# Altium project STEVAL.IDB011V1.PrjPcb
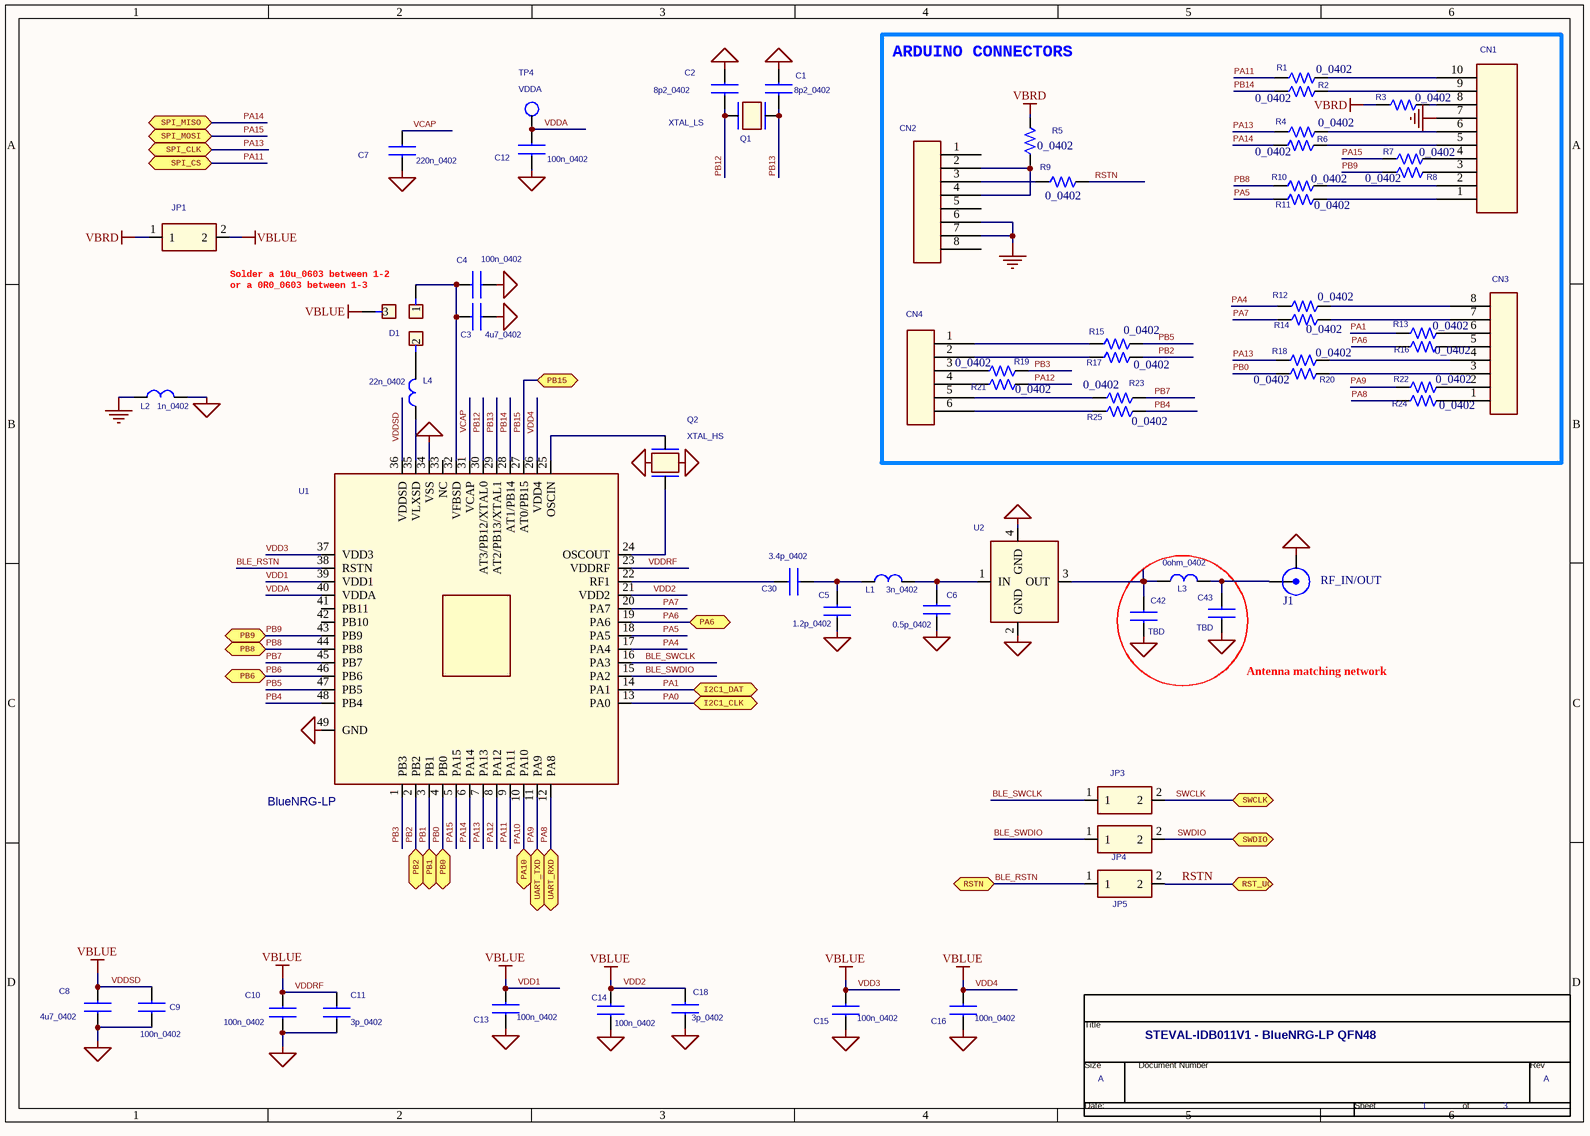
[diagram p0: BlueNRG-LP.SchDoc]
3 sheets, 158 parts. Net scope: flat (ports and power ports of the same name join across sheets).
Board file: STEVAL-IDB011V1.PcbDoc
Sheets:
  BlueNRG-LP.SchDoc
  Supply.SchDoc
  USB_MICRO.SchDoc

## Sheet BlueNRG-LP.SchDoc
size 297 x 209 mm

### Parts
(Parts that share a designator on the sheet are numbered #1, #2 ... from top to bottom, then left to right.)
*#1  Page Count: 3  Page Number: 1  Page Size: A  Title: STEVAL-IDB011V1 - BlueNRG-LP QFN48  (hidden comment: TitleBlock0)  (graphical)
C1  8p2_0402  [0402_CAP_NP]
C2  8p2_0402  [0402_CAP_NP]
C3  4u7_0402  [0402_CAP_NP]
C4  100n_0402  [0402_CAP_NP]
C5  1.2p_0402  [0402_CAP_NP]
C6  0.5p_0402  [0402_CAP_NP]
C7  220n_0402  [0402_CAP_NP]
C8  4u7_0402  [0402_CAP_NP]
C9  100n_0402  [0402_CAP_NP]
C10  100n_0402  [0402_CAP_NP]
C11  3p_0402  [0402_CAP_NP]
C12  100n_0402  [0402_CAP_NP]
C13  100n_0402  [0402_CAP_NP]
C14  100n_0402  [0402_CAP_NP]
C15  100n_0402  [0402_CAP_NP]
C16  100n_0402  [0402_CAP_NP]
C18  3p_0402  [0402_CAP_NP]
C30  3.4p_0402  [0402_CAP_NP]
C42  TBD  [0402_CAP_NP]
C43  TBD  [0402_CAP_NP]
CN1  CON10  [HDR1X10]  (value not drawn)
CN2  CON8  [HDR1X8]  (value not drawn)
CN3  CON8  [HDR1X8]  (value not drawn)
CN4  CON6  [HDR1X6]  (value not drawn)
D1  DEV3L  [DEV3L0603]  (value not drawn)
J1  RF_IN/OUT  [SMA Johonson 142-0701-841]
JP1  JUMPER 2  [HDR 2 X 1 M]  (value not drawn)
JP3  JUMPER 2  [HDR 2 X 1 M]  (value not drawn)
JP4  JUMPER 2  [HDR 2 X 1 M]  (value not drawn)
JP5  JUMPER 2  [HDR 2 X 1 M]  (value not drawn)
L1  3n_0402  [0402-A]
L2  1n_0402  [0402-A]
L3  0ohm_0402  [0402-A]
L4  22n_0402  [0402-A]
Q1  XTAL_LS  [NX2012SA]
Q2  XTAL_HS  [NX2016SA]
R1  0_0402
R2  0_0402
R3  0_0402
R4  0_0402
R5  0_0402
R6  0_0402
R7  0_0402
R8  0_0402
R9  0_0402
R10  0_0402
R11  0_0402
R12  0_0402
R13  0_0402
R14  0_0402
R15  0_0402
R16  0_0402
R17  0_0402
R18  0_0402
R19  0_0402
R20  0_0402
R21  0_0402
R22  0_0402
R23  0_0402
R24  0_0402
R25  0_0402
TP4  VDDA  [FIDUCIAL]
U1  BlueNRG-LP  [QFN48_6X6]
U2  (no value)  [DLF162500LT]

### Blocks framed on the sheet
ARDUINO CONNECTORS: CN1-CN4 R1-R25

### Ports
I2C1_CLK (bidir), I2C1_DAT (bidir), PA6 (bidir), PA10 (bidir), PB0 (bidir), PB1 (bidir), PB2 (bidir), PB6 (bidir), PB8 (bidir), PB9 (bidir), PB15 (bidir), RST_UC (bidir), RSTN (bidir), SPI_CLK (bidir), SPI_CS (bidir), SPI_MISO (bidir), SPI_MOSI (bidir), SWCLK (bidir), SWDIO (bidir), UART_RXD (bidir), UART_TXD (bidir)

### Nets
GND: CN1.7 CN2.6 CN2.7 L2.1
GND_RF: C1.1 C2.1 C3.1 C4.1 C5.1 C6.1 C7.1 C8.1 C9.1 C10.1 C11.1 C12.1 C13.1 C14.1 C15.1 C16.1 C18.1 C42.1 C43.1 J1.2(Y) L2.2 Q2.2 Q2.4(gnd1) U1.34(VSS) U1.49(GND) U2.2(GND) U2.4(GND)
VBRD: JP1.1 R3.1 R5.2  [project net VDD_1]
VDD1: C8.2 C9.2 C10.2 C11.2 C13.2 C14.2 C15.2 C16.2 C18.2 D1.3 JP1.2 U1.21(VDD2) U1.23(VDDRF) U1.26(VDD4) U1.36(VDDSD) U1.37(VDD3) U1.39(VDD1)  [also labelled VBLUE, VDD2, VDD3, VDD4, VDDRF, VDDSD]
BLE_RSTN: JP5.1 U1.38(RSTN) ; port RSTN
BLE_SWCLK: JP3.1 U1.16(PA3)
BLE_SWDIO: JP4.1 U1.15(PA2)
PA0: U1.13(PA0) ; port I2C1_CLK
PA1: R13.1 U1.14(PA1) ; port I2C1_DAT
PA4: R12.1 U1.17(PA4)
PA5: R11.1 U1.18(PA5)
PA6: R16.1 U1.19(PA6) ; port PA6
PA7: R14.1 U1.20(PA7)
PA8: R24.1 U1.12(PA8) ; port UART_RXD
PA9: R22.1 U1.11(PA9) ; port UART_TXD
PA10: U1.10(PA10) ; port PA10
PA11: R1.1 U1.9(PA11) ; port SPI_CS
PA12: R21.2 U1.8(PA12)
PA13: R4.1 R18.1 U1.7(PA13) ; port SPI_CLK
PA14: R6.1 U1.6(PA14) ; port SPI_MISO
PA15: R7.1 U1.5(PA15) ; port SPI_MOSI
PB0: R20.1 U1.4(PB0) ; port PB0
PB1: U1.3(PB1) ; port PB1
PB2: R17.2 U1.2(PB2) ; port PB2
PB3: R19.2 U1.1(PB3)
PB4: R25.2 U1.48(PB4)
PB5: R15.2 U1.47(PB5)
PB6: U1.46(PB6) ; port PB6
PB7: R23.2 U1.45(PB7)
PB8: R10.1 U1.44(PB8) ; port PB8
PB9: R8.1 U1.43(PB9) ; port PB9
PB12: C2.2 Q1.1 U1.30(AT3/PB12/XTAL0)
PB13: C1.2 Q1.2 U1.29(AT2/PB13/XTAL1)
PB14: R2.1 U1.28(AT1/PB14)
PB15: U1.27(AT0/PB15) ; port PB15
RSTN: JP5.2 R9.2 ; port RST_UC
SWCLK: JP3.2 ; port SWCLK
SWDIO: JP4.2 ; port SWDIO
VCAP: C7.2 U1.31(VCAP)
VDDA: C12.2 TP4.1(TP) U1.40(VDDA)
NetC3_2: C3.2 C4.2 D1.1 U1.32(VFBSD)
NetC5_2: C5.2 C30.1 L1.1
NetC6_2: C6.2 L1.2 U2.1(IN)
NetC30_2: C30.2 U1.22(RF1)
NetC42_2: C42.2 L3.1 U2.3(OUT)
NetC43_2: C43.2 J1.1(X) L3.2
NetCN1_1: CN1.1 R11.2
NetCN1_2: CN1.2 R10.2
NetCN1_3: CN1.3 R8.2
NetCN1_4: CN1.4 R7.2
NetCN1_5: CN1.5 R6.2
NetCN1_6: CN1.6 R4.2
NetCN1_8: CN1.8 R3.2
NetCN1_9: CN1.9 R2.2
NetCN1_10: CN1.10 R1.2
NetCN2_2: CN2.2 CN2.4 R5.1
NetCN2_3: CN2.3 R9.1
NetCN3_1: CN3.1 R24.2
NetCN3_2: CN3.2 R22.2
NetCN3_3: CN3.3 R20.2
NetCN3_4: CN3.4 R18.2
NetCN3_5: CN3.5 R16.2
NetCN3_6: CN3.6 R13.2
NetCN3_7: CN3.7 R14.2
NetCN3_8: CN3.8 R12.2
NetCN4_1: CN4.1 R15.1
NetCN4_2: CN4.2 R17.1
NetCN4_3: CN4.3 R19.1
NetCN4_4: CN4.4 R21.1
NetCN4_5: CN4.5 R23.1
NetCN4_6: CN4.6 R25.1
NetD1_2: D1.2 L4.2
NetL4_1: L4.1 U1.35(VLXSD)
NetQ2_1: Q2.1 U1.25(OSCIN)
NetQ2_3: Q2.3 U1.24(OSCOUT)

Not connected (* = marked no-connect by the designer): CN2 1 5 8; U1 33(NC) 41(PB11) 42(PB10)

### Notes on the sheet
- (near D1) Solder a 10u_0603 between 1-2
  or a 0R0_0603 between 1-3
- (near C43) Antenna matching network

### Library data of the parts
*#1 = TitleBlock0: Doc: BLUENRG-248 APPLICATION BOARD
C1 C6 C10 C12 C13 = MURATA GRM36: COMPSIDE: TOP; COMPLOC: [-1955.000,605.000]; COMPROT: 180; COMPGROUP: 0; COMPFIXED: NO; COMPHEIGHT: 0.000
C2-C5 C7-C9 C11 C14-C16 C18 C30 C42 C43 = MURATA GRM36: COMPHEIGHT: 0.000; MEMORY: NO; COMPGROUP: 0; COMPROT: 180; COMPLOC: [-1955.000,605.000]; COMPSIDE: TOP
D1 = DEV3L_0
J1 = SMA_Molex: 50 Ohms, SMA Jack Receptacle, Edge Mount, .25µm Gold (Au) Plating; Manufacturer: Molex; Manufacturer’s ordering code / Orderable Part Number: 73251-1150; STEVAL: FKIxxx; Value: SMA_RF
JP1 JP3-JP5 = Buzzer
L1-L4 = IND_short
Q1 = QUARZO
Q2 = NX3225SA: COMPSIDE: TOP; COMPLOC: [-2158.000,974.000]; COMPROT: 180; COMPGROUP: 0; COMPFIXED: NO; COMPHEIGHT: 0.000
R1-R25 = R_Dup1: PSpiceTemplate: R^@REFDES %1 %2 ?TOLERANCE¦R^@REFDES¦ @VALUE  ?TOLERANCE¦\n.model R^@REFDES RES R=1 DEV=@TOLERANCE%¦
TP4 = T POINT R: COMPHEIGHT: 10.000; MEMORY: NO; COMPGROUP: 0; COMPROT: 270; COMPLOC: [734.867,493.467]; COMPSIDE: TOP
U1 = BlueNRG-LP_QFN48_0
U2 = DLF162500LT

## Sheet Supply.SchDoc
size 297 x 209 mm
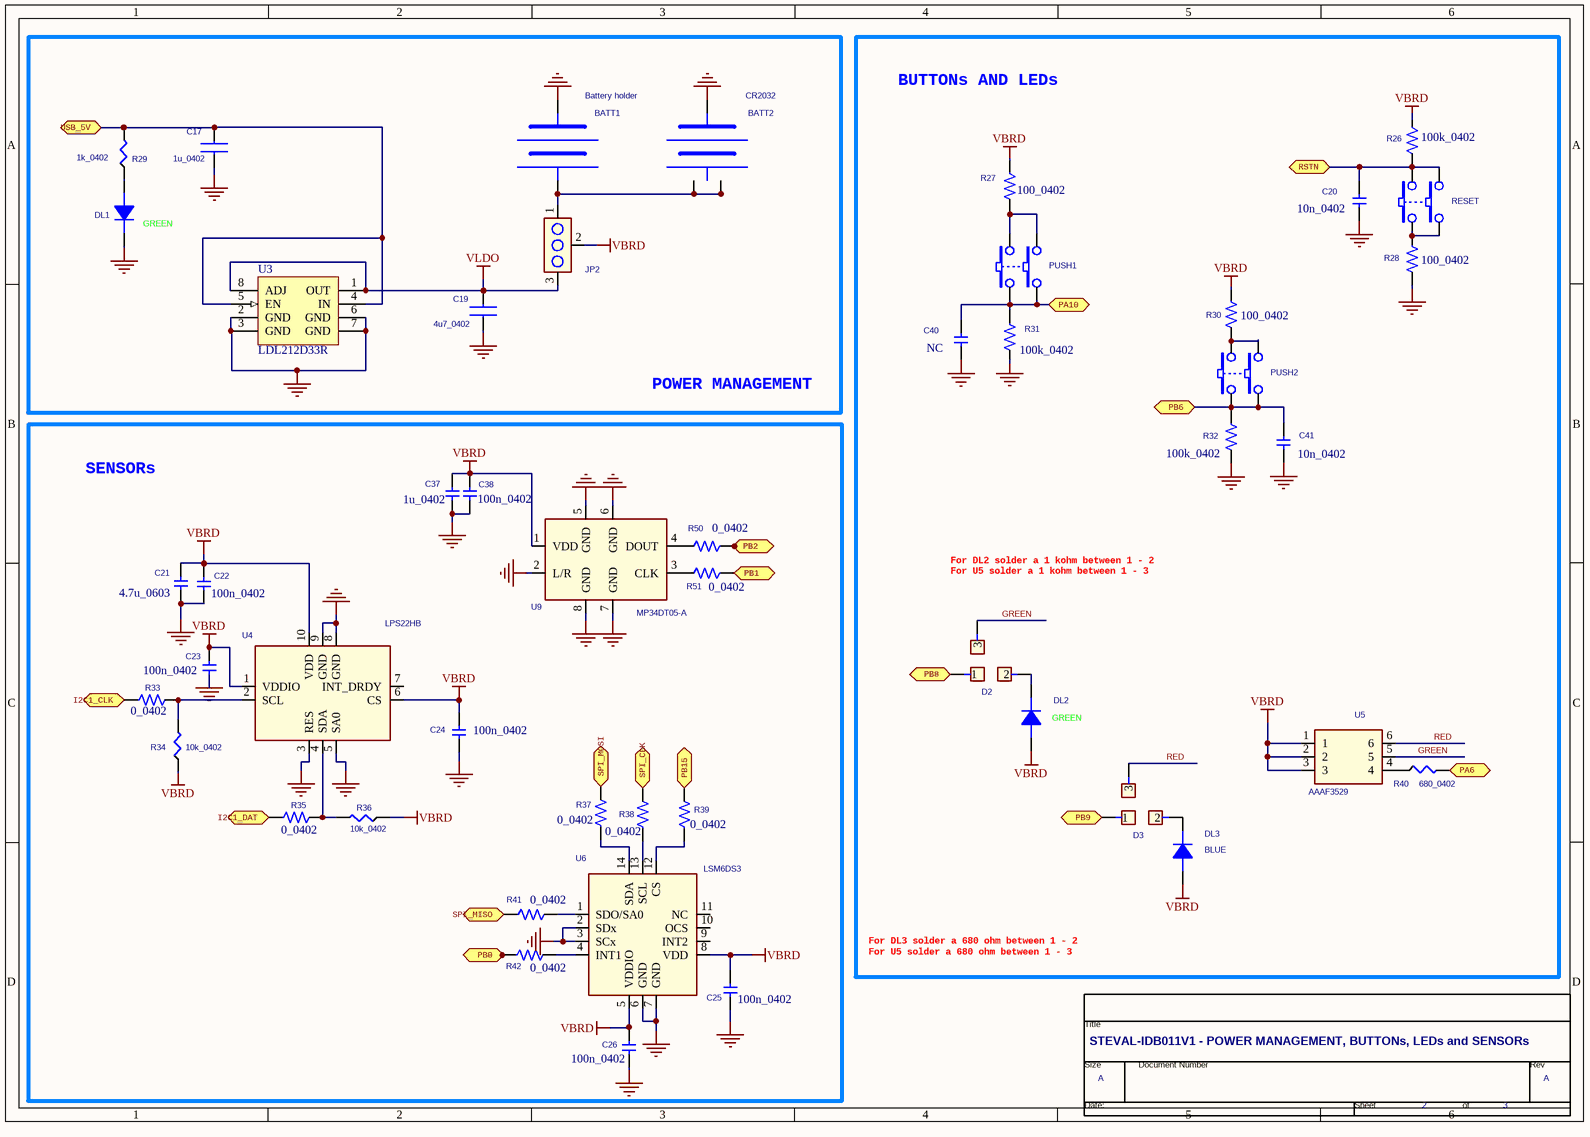
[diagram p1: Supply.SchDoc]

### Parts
(Parts that share a designator on the sheet are numbered #1, #2 ... from top to bottom, then left to right.)
*#2  Page Count: 3  Page Number: 2  Page Size: A  Title: STEVAL-IDB011V1 - POWER MANAGEMENT, BUTTONs, LEDs and SENSORs  (hidden comment: TitleBlock0)  (graphical)
BATT1  Battery holder  [PACCO_BATT_2]
BATT2  CR2032  [CR2032_BATTERY_HOLDER]
C17  1u_0402  [0402_CAP_NP]
C19  4u7_0402  [0402_CAP_NP]
C20  10n_0402  [0402_CAP_NP]
C21  4.7u_0603  [0603_CAP_NP]
C22  100n_0402  [0402_CAP_NP]
C23  100n_0402  [0402_CAP_NP]
C24  100n_0402  [0402_CAP_NP]
C25  100n_0402  [0402_CAP_NP]
C26  100n_0402  [0402_CAP_NP]
C37  1u_0402  [0402_CAP_NP]
C38  100n_0402  [0402_CAP_NP]
C40  NC  [0402_CAP_NP]
C41  10n_0402  [0402_CAP_NP]
D2  DEV3L  [DEV3L0603]  (value not drawn)
D3  DEV3L  [DEV3L0603]  (value not drawn)
DL1  Diodo_led  [SMD _LED]  (value not drawn)
DL2  Diodo_led  [SMD _LED]  (value not drawn)
DL3  BLUE  [SMD _LED]
JP2  Jumper 3  [HDR 3 X 1 M]  (value not drawn)
R26  100k_0402
R27  100_0402
R28  100_0402
R29  1k_0402  [0402_CAP_NP]
R30  100_0402
R31  100k_0402
R32  100k_0402
R33  0_0402
R34  10k_0402  [0402_CAP_NP]
R35  0_0402
R36  10k_0402  [0402_CAP_NP]
R37  0_0402
R38  0_0402
R39  0_0402
R40  680_0402  [0402_CAP_NP]
R41  0_0402
R42  0_0402
R50  value 0_0402  (hidden comment: NC)
R51  value 0_0402  (hidden comment: NC)
SW1  RESET  [B3FS_SWITCH]
SW2  PUSH1  [B3FS_SWITCH]
SW3  PUSH2  [B3FS_SWITCH]
U3  LDL212D33R  [SO8_N]
U4  LPS22HB  [HLGA-10L-2X2]
U5  AAAF3529  [AAAF3529L]
U6  LSM6DS3  [LGA14]
U9  MP34DT05-A  [MP34DT05-A]

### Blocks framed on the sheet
POWER MANAGEMENT: BATT1 BATT2 C17 C19 DL1 JP2 R29 U3
BUTTONs AND LEDs: C20 C40 C41 D2 D3 DL2 DL3 R26-R28 R30-R32 R40 SW1-SW3 U5
SENSORs: C21-C26 C37 C38 R33-R39 R41 R42 R50 R51 U4 U6 U9

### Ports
I2C1_CLK (bidir), I2C1_DAT (bidir), PA6 (bidir), PA10 (bidir), PB0 (bidir), PB1 (bidir), PB2 (bidir), PB6 (bidir), PB8 (bidir), PB9 (bidir), PB15 (bidir), RSTN (bidir), SPI_CLK (bidir), SPI_MISO (bidir), SPI_MOSI (bidir), USB_5V (bidir)

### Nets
GND: BATT1.2(GND) BATT2.3(GND) C17.1 C19.1 C20.1 C21.1 C22.1 C23.1 C24.1 C25.1 C26.1 C37.1 C38.1 C40.1 C41.1 DL1.2(CATHODE) R28.2 R31.2 R32.2 U3.2(GND) U3.3(GND) U3.6(GND) U3.7(GND) U4.3(RES) U4.5(SA0) U4.8(GND) U4.9(GND) U6.2(SDx) U6.3(SCx) U6.6(GND) U6.7(GND) U9.2(L/R) U9.5(GND) U9.6(GND) U9.7(GND) U9.8(GND)
VBRD: C21.2 C22.2 C23.2 C24.2 C25.2 C26.2 C37.2 C38.2 DL2.1(ANODE) DL3.1(ANODE) JP2.2 R26.1 R27.1 R30.1 R34.1 R36.1 U4.1(VDDIO) U4.6(CS) U4.10(VDD) U5.1 U5.2 U5.3 U6.5(VDDIO) U6.8(VDD) U9.1(VDD)  [project net VDD_1]
VLDO: C19.2 JP2.3 U3.1(OUT) U3.8(ADJ)
BLE_RSTN: C20.2 R26.2 SW1.3 SW1.4 ; port RSTN
GREEN: D2.3 U5.5
PA0: R33.1 ; port I2C1_CLK
PA1: R35.1 ; port I2C1_DAT
PA6: R40.2 ; port PA6
PA10: C40.2 R31.1 SW2.1 SW2.2 ; port PA10
PA13: R38.2 ; port SPI_CLK
PA14: R41.1 ; port SPI_MISO
PA15: R37.2 ; port SPI_MOSI
PB0: R42.1 ; port PB0
PB1: R51.1 ; port PB1
PB2: R50.1 ; port PB2
PB6: C41.2 R32.1 SW3.1 SW3.2 ; port PB6
PB8: D2.1 ; port PB8
PB9: D3.1 ; port PB9
PB15: R39.2 ; port PB15
RED: D3.3 U5.6
NetBATT1_1: BATT1.1(VP) BATT2.1(VP) BATT2.2(VP) JP2.1
NetC17_2: C17.2 R29.2 U3.4(IN) U3.5(EN) ; port USB_5V
NetD2_2: D2.2 DL2.2(CATHODE)
NetD3_2: D3.2 DL3.2(CATHODE)
NetDL1_1: DL1.1(ANODE) R29.1
NetR27_2: R27.2 SW2.3 SW2.4
NetR28_1: R28.1 SW1.1 SW1.2
NetR30_2: R30.2 SW3.3 SW3.4
NetR33_2: R33.2 R34.2 U4.2(SCL)
NetR35_2: R35.2 R36.2 U4.4(SDA)
NetR37_1: R37.1 U6.14(SDA)
NetR38_1: R38.1 U6.13(SCL)
NetR39_1: R39.1 U6.12(CS)
NetR40_1: R40.1 U5.4
NetR41_2: R41.2 U6.1(SDO/SA0)
NetR42_2: R42.2 U6.4(INT1)
NetR50_2: R50.2 U9.4(DOUT)
NetR51_2: R51.2 U9.3(CLK)

Not connected (* = marked no-connect by the designer): U4 7(INT_DRDY); U6 9(INT2) 10(OCS) 11(NC)

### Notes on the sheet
- (near DL1) GREEN
- (near D2) For DL2 solder a 1 kohm between 1 - 2
  For U5 solder a 1 kohm between 1 - 3
- (near DL2) GREEN
- (near *#2) For DL3 solder a 680 ohm between 1 - 2
  For U5 solder a 680 ohm between 1 - 3

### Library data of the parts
*#2 = TitleBlock0: Doc: BLUENRG-2 APPLICATION BOARD
BATT2 = Battery holder_0
C17 = MURATA GRM36: as C2 on sheet BlueNRG-LP
C19 = MURATA GRM36: as C1 on sheet BlueNRG-LP
C20 C40 C41 = C: PSpiceTemplate: C^@REFDES %1 %2 ?TOLERANCE¦C^@REFDES¦ @VALUE ?IC/IC=@IC/ ?TOLERANCE¦\n.model C^@REFDES CAP C=1 DEV=@TOLERANCE%¦; COMPSIDE: TOP; COMPLOC: [-4703.000,-13410.000]; COMPROT: 270; COMPGROUP: 0; COMPFIXED: NO; COMPHEIGHT: 0.000
C21 C23 C25 C26 C38 = C: PSpiceTemplate: C^@REFDES %1 %2 ?TOLERANCE¦C^@REFDES¦ @VALUE ?IC/IC=@IC/ ?TOLERANCE¦\n.model C^@REFDES CAP C=1 DEV=@TOLERANCE%¦; COMPHEIGHT: 0.000; MEMORY: NO; COMPGROUP: 0; COMPROT: 270; COMPLOC: [-4302.000,-13410.000]; COMPSIDE: TOP
C22 C24 C37 = C: PSpiceTemplate: C^@REFDES %1 %2 ?TOLERANCE¦C^@REFDES¦ @VALUE ?IC/IC=@IC/ ?TOLERANCE¦\n.model C^@REFDES CAP C=1 DEV=@TOLERANCE%¦; COMPSIDE: TOP; COMPLOC: [-4302.000,-13410.000]; COMPROT: 270; COMPGROUP: 0; COMPFIXED: NO; COMPHEIGHT: 0.000
D2 D3 = DEV3L_0
DL1 = Diodo_led: COMPSIDE: TOP; COMPLOC: [607.800,3484.867]; COMPROT: 0; COMPFIXED: NO; COMPHEIGHT: 0.000
DL2 = Diodo_led: COMPHEIGHT: 0.000; MEMORY: NO; COMPGROUP: 0; COMPLOC: [607.800,3484.867]; COMPSIDE: TOP
DL3 = Diodo_led: FPLIST: SM/D1206_S; COMPSIDE: TOP; COMPLOC: [1254.733,908.600]; COMPROT: 270; COMPGROUP: 0; COMPFIXED: NO; COMPHEIGHT: 0.000
R26 = R_Dup1: PSpiceTemplate: R^@REFDES %1 %2 ?TOLERANCE¦R^@REFDES¦ @VALUE  ?TOLERANCE¦\n.model R^@REFDES RES R=1 DEV=@TOLERANCE%¦; COMPSIDE: TOP; COMPLOC: [-4614.000,-13410.000]; COMPROT: 270; COMPGROUP: 0; COMPFIXED: NO; COMPHEIGHT: 0.000
R27 = R_Dup1: PSpiceTemplate: R^@REFDES %1 %2 ?TOLERANCE¦R^@REFDES¦ @VALUE  ?TOLERANCE¦\n.model R^@REFDES RES R=1 DEV=@TOLERANCE%¦; COMPSIDE: TOP; COMPLOC: [-4218.000,-13410.000]; COMPROT: 270; COMPGROUP: 0; COMPFIXED: NO; COMPHEIGHT: 0.000
R28 = R_Dup1: PSpiceTemplate: R^@REFDES %1 %2 ?TOLERANCE¦R^@REFDES¦ @VALUE  ?TOLERANCE¦\n.model R^@REFDES RES R=1 DEV=@TOLERANCE%¦; COMPHEIGHT: 0.000; MEMORY: NO; COMPGROUP: 0; COMPROT: 90; COMPLOC: [-4786.000,-13465.000]; COMPSIDE: TOP
R29 = R: COMPSIDE: TOP; COMPLOC: [1164.933,2712.533]; COMPROT: 0; COMPFIXED: NO; COMPHEIGHT: 0.000
R30 = R_Dup1: PSpiceTemplate: R^@REFDES %1 %2 ?TOLERANCE¦R^@REFDES¦ @VALUE  ?TOLERANCE¦\n.model R^@REFDES RES R=1 DEV=@TOLERANCE%¦; COMPHEIGHT: 0.000; MEMORY: NO; COMPGROUP: 0; COMPROT: 270; COMPLOC: [-4614.000,-13410.000]; COMPSIDE: TOP
R31 = R_Dup1: PSpiceTemplate: R^@REFDES %1 %2 ?TOLERANCE¦R^@REFDES¦ @VALUE  ?TOLERANCE¦\n.model R^@REFDES RES R=1 DEV=@TOLERANCE%¦; COMPSIDE: TOP; COMPLOC: [-4389.000,-13465.000]; COMPROT: 90; COMPGROUP: 0; COMPFIXED: NO; COMPHEIGHT: 0.000
R32 = R_Dup1: PSpiceTemplate: R^@REFDES %1 %2 ?TOLERANCE¦R^@REFDES¦ @VALUE  ?TOLERANCE¦\n.model R^@REFDES RES R=1 DEV=@TOLERANCE%¦; COMPSIDE: TOP; COMPLOC: [-4786.000,-13465.000]; COMPROT: 90; COMPGROUP: 0; COMPFIXED: NO; COMPHEIGHT: 0.000
R33 R35 R37-R39 R41 R42 R50 R51 = R_Dup1: as R1 on sheet BlueNRG-LP
R34 R36 = R: FPLIST: SM/R_0805; COMPSIDE: TOP; COMPLOC: [1528.600,2164.067]; COMPROT: 180; COMPGROUP: 0; COMPFIXED: NO; COMPHEIGHT: 0.000
R40 = R: FPLIST: SM/R_0805; COMPSIDE: TOP; COMPLOC: [1529.600,1899.067]; COMPROT: 180; COMPGROUP: 0; COMPFIXED: NO; COMPHEIGHT: 0.000
SW1 = SWITCH-1: COMPHEIGHT: 8.000; MEMORY: NO; COMPGROUP: 0; COMPLOC: [-4725.000,-13849.000]; COMPSIDE: TOP; FPLIST: PULSE2_479-1508
SW2 SW3 = SWITCH-1: FPLIST: PULSE2_479-1508; COMPSIDE: TOP; COMPLOC: [-4725.000,-13849.000]; COMPROT: 0; COMPFIXED: NO; COMPHEIGHT: 8.000
U3 = KF15BD: Very Low Drop Voltage Regulator with Inhibit
U4 = LPS25HB
U9 = MP34DT05-A_0

## Sheet USB_MICRO.SchDoc
size 297 x 209 mm
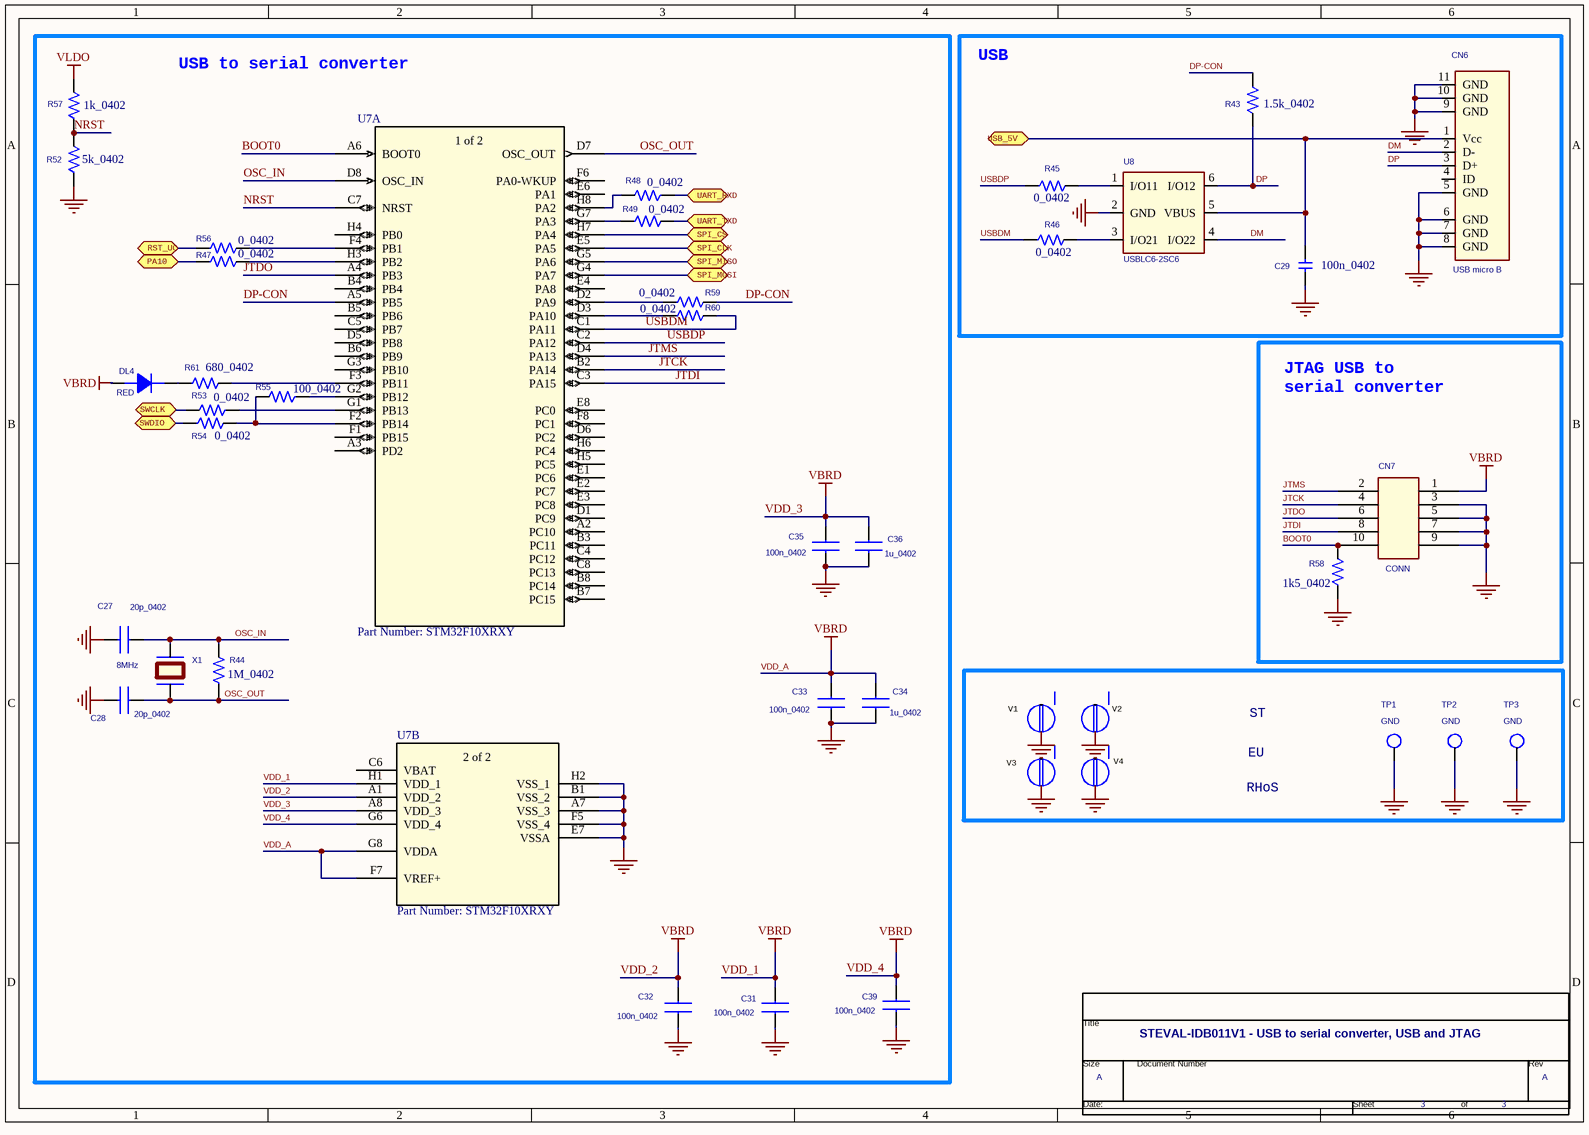
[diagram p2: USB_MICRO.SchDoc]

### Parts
(Parts that share a designator on the sheet are numbered #1, #2 ... from top to bottom, then left to right.)
*#3  Page Count: 3  Page Size: A  Title: STEVAL-IDB011V1 - USB to serial converter, USB and JTAG  (hidden comment: TitleBlock0)  (graphical)
C27  20p_0402  [0402_CAP_NP]
C28  20p_0402  [0402_CAP_NP]
C29  100n_0402  [0402_CAP_NP]
C31  100n_0402  [0402_CAP_NP]
C32  100n_0402  [0402_CAP_NP]
C33  100n_0402  [0402_CAP_NP]
C34  1u_0402  [0402_CAP_NP]
C35  100n_0402  [0402_CAP_NP]
C36  1u_0402  [0402_CAP_NP]
C39  100n_0402  [0402_CAP_NP]
CN6  USB micro B  [MICRO USB]
CN7  CONN  [AMPMODE10_50M]
DL4  RED  [SMD _LED]
R43  1.5k_0402
R44  1M_0402
R45  0_0402
R46  0_0402
R47  0_0402
R48  0_0402
R49  0_0402
R52  5k_0402
R53  0_0402
R54  0_0402
R55  100_0402
R56  0_0402
R57  1k_0402
R58  1k5_0402
R59  0_0402
R60  0_0402
R61  680_0402
ST1  stlogo  [stlogo]  (value not drawn)
ST2  EUlogo  [EU_ROHS_1_2]  (value not drawn)
ST3  RHoSlogo  [CH_ROHS_2]  (value not drawn)
TP1  GND  [TESTP]
TP2  GND  [TESTP]
TP3  GND  [TESTP]
U7  Part Number: STM32F10XRXY  [PCBComponent_1]  (parts A,B of 2)
U8  USBLC6-2SC6  [SOT23-6L_S]
V1  VITE  [FORO 3MM]  (value not drawn)
V2  VITE  [FORO 3MM]  (value not drawn)
V3  VITE  [FORO 3MM]  (value not drawn)
V4  VITE  [FORO 3MM]  (value not drawn)
X1  8MHz  [QUARZO]

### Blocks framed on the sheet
USB to serial converter: C27 C28 C31-C36 C39 DL4 R44 R47-R49 R52-R57 R59-R61 U7 X1
USB: C29 CN6 R43 R45 R46 U8

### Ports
PA10 (bidir), RST_UC (bidir), SPI_CLK (bidir), SPI_CS (bidir), SPI_MISO (bidir), SPI_MOSI (bidir), SWCLK (bidir), SWDIO (bidir), UART_RXD (bidir), UART_TXD (bidir), USB_5V (bidir)

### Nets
GND: C27.2 C28.2 C29.2 C31.1 C32.1 C33.1 C34.1 C35.1 C36.1 C39.1 CN6.5(GND) CN6.6(GND) CN6.7(GND) CN6.8(GND) CN6.9(GND) CN6.10(GND) CN6.11(GND) CN7.3(+) CN7.5(+) CN7.7(+) CN7.9(+) R52.1 R58.1 TP1.1(TP) TP2.1(TP) TP3.1(TP) U7.A7(VSS_3) U7.B1(VSS_2) U7.E7(VSSA) U7.F5(VSS_4) U7.H2(VSS_1) U8.2(GND) V1.1 V2.1 V3.1 V4.1
VDD_1: C31.2 C32.2 C33.2 C34.2 C35.2 C36.2 C39.2 CN7.1(+) DL4.1(ANODE) U7.A1(VDD_2) U7.A8(VDD_3) U7.F7(VREF+) U7.G6(VDD_4) U7.G8(VDDA) U7.H1(VDD_1)  [also labelled VBRD, VDD_2, VDD_3, VDD_4, VDD_A]
VLDO: R57.2
BOOT0: CN7.10(+) R58.2 U7.A6(BOOT0)
DM: CN6.2(D-) U8.4(I/O22)
DP: CN6.3(D+) R43.2 U8.6(I/O12)
DP-CON: R43.1 R59.2 U7.A5(PB5)
JTCK: CN7.4(+) U7.B2(PA14)
JTDI: CN7.8(+) U7.C3(PA15)
JTDO: CN7.6(+) U7.A4(PB3)
JTMS: CN7.2(+) U7.D4(PA13)
NRST: R52.2 R57.1 U7.C7(NRST)
OSC_IN: C27.1 R44.2 U7.D8(OSC_IN) X1.2
OSC_OUT: C28.1 R44.1 U7.D7(OSC_OUT) X1.1
PA8: R48.1 ; port UART_RXD
PA9: R49.2 ; port UART_TXD
PA10: R47.1 ; port PA10
PA11: U7.H7(PA4) ; port SPI_CS
PA13: U7.E5(PA5) ; port SPI_CLK
PA14: U7.G5(PA6) ; port SPI_MISO
PA15: U7.G4(PA7) ; port SPI_MOSI
RSTN: R56.1 ; port RST_UC
SWCLK: R53.2 ; port SWCLK
SWDIO: R54.1 ; port SWDIO
USBDM: R46.1 R60.2 U7.C1(PA11)
USBDP: R45.1 U7.C2(PA12)
NetC17_2: C29.1 CN6.1(Vcc) U8.5(VBUS) ; port USB_5V
NetDL4_2: DL4.2(CATHODE) R61.1
NetR45_2: R45.2 U8.1(I/O11)
NetR46_2: R46.2 U8.3(I/O21)
NetR47_2: R47.2 U7.H3(PB2)
NetR48_2: R48.2 U7.H8(PA2)
NetR49_1: R49.1 U7.G7(PA3)
NetR53_1: R53.1 U7.G1(PB13)
NetR54_2: R54.2 R55.2 U7.F2(PB14)
NetR55_1: R55.1 U7.G2(PB12)
NetR56_2: R56.2 U7.F4(PB1)
NetR59_1: R59.1 U7.D2(PA9)
NetR60_1: R60.1 U7.D3(PA10)
NetR61_2: R61.2 U7.F3(PB11)

Not connected (* = marked no-connect by the designer): CN6 4(ID); U7 A2(PC10) A3(PD2) B3(PC11) B4(PB4) B5(PB6) B6(PB9) B7(PC15) B8(PC14) C4(PC12) C5(PB7) C6(VBAT) C8(PC13) D1(PC9) D5(PB8) D6(PC2) E1(PC6) E2(PC7) E3(PC8) E4(PA8) E6(PA1) E8(PC0) F1(PB15) F6(PA0-WKUP) F8(PC1) G3(PB10) H4(PB0) H5(PC5) H6(PC4)

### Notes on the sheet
- JTAG USB to
  serial converter
- (near V1) V1
- (near V2) V2
- V3
- V4

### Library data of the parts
*#3 = TitleBlock0: Doc: BLUENRG-2 APPLICATION BOARD
C27 C28 C31 C34 C36 C39 = MURATA GRM36: as C2 on sheet BlueNRG-LP
C29 = C: PSpiceTemplate: C^@REFDES %1 %2 ?TOLERANCE¦C^@REFDES¦ @VALUE ?IC/IC=@IC/ ?TOLERANCE¦\n.model C^@REFDES CAP C=1 DEV=@TOLERANCE%¦; COMPHEIGHT: 0.000; MEMORY: NO; COMPGROUP: 0; COMPROT: 270; COMPLOC: [814.800,3196.200]; COMPSIDE: TOP
C32 C33 C35 = MURATA GRM36: as C1 on sheet BlueNRG-LP
CN6 = USB micro B_0
CN7 = CON10AP
DL4 = Diodo_led: as DL3 on sheet Supply
R43 = R_Dup1: PSpiceTemplate: R^@REFDES %1 %2 ?TOLERANCE¦R^@REFDES¦ @VALUE  ?TOLERANCE¦\n.model R^@REFDES RES R=1 DEV=@TOLERANCE%¦; COMPHEIGHT: 0.000; MEMORY: NO; COMPGROUP: 0; COMPROT: 180; COMPLOC: [1050.667,2713.533]; COMPSIDE: TOP
R44 R45 = R_Dup1: PSpiceTemplate: R^@REFDES %1 %2 ?TOLERANCE¦R^@REFDES¦ @VALUE  ?TOLERANCE¦\n.model R^@REFDES RES R=1 DEV=@TOLERANCE%¦; COMPHEIGHT: 0.000; MEMORY: NO; COMPGROUP: 0; COMPROT: 180; COMPLOC: [1051.533,2790.267]; COMPSIDE: TOP
R46 R52 R57 R58 R60 R61 = R_Dup1: PSpiceTemplate: R^@REFDES %1 %2 ?TOLERANCE¦R^@REFDES¦ @VALUE  ?TOLERANCE¦\n.model R^@REFDES RES R=1 DEV=@TOLERANCE%¦; COMPHEIGHT: 0.000; MEMORY: NO; COMPGROUP: 0; COMPROT: 180; COMPLOC: [1219.333,2792.667]; COMPSIDE: TOP
R47-R49 R56 = R_Dup1: as R1 on sheet BlueNRG-LP
R53-R55 R59 = R_Dup1: PSpiceTemplate: R^@REFDES %1 %2 ?TOLERANCE¦R^@REFDES¦ @VALUE  ?TOLERANCE¦\n.model R^@REFDES RES R=1 DEV=@TOLERANCE%¦; COMPSIDE: TOP; COMPLOC: [1219.333,2792.667]; COMPROT: 180; COMPGROUP: 0; COMPFIXED: NO; COMPHEIGHT: 0.000
TP1 = T POINT R: COMPHEIGHT: 10.000; MEMORY: NO; COMPGROUP: 0; COMPROT: 270; COMPLOC: [1368.800,3252.867]; COMPSIDE: TOP
TP2 = T POINT R: COMPHEIGHT: 10.000; MEMORY: NO; COMPGROUP: 0; COMPROT: 270; COMPLOC: [3983.400,3545.533]; COMPSIDE: TOP
TP3 = T POINT R: COMPSIDE: TOP; COMPLOC: [734.867,493.467]; COMPROT: 270; COMPGROUP: 0; COMPFIXED: NO; COMPHEIGHT: 10.000
U7 = STM32F10XRXY: No Description Available; Vendor: STMicroelectronics
U8 = USBUFxxW6_0: COMPSIDE: TOP; COMPLOC: [940.933,3064.267]; COMPROT: 90; COMPGROUP: 0; COMPFIXED: NO; COMPHEIGHT: 0.000
V1 = VITE: COMPSIDE: TOP; COMPLOC: [3951.133,401.533]; COMPROT: 0; COMPFIXED: NO; COMPHEIGHT: 0.000
V2 = VITE: COMPSIDE: TOP; COMPLOC: [460.000,401.533]; COMPROT: 0; COMPFIXED: NO; COMPHEIGHT: 0.000
V3 = VITE: COMPSIDE: TOP; COMPLOC: [3942.867,4490.733]; COMPROT: 0; COMPFIXED: NO; COMPHEIGHT: 0.000
V4 = VITE: COMPSIDE: TOP; COMPLOC: [460.000,4504.667]; COMPROT: 0; COMPFIXED: NO; COMPHEIGHT: 0.000
X1 = QUARZO_Dup1: COMPSIDE: TOP; COMPLOC: [-4326.000,-12933.000]; COMPROT: 0; COMPFIXED: NO; COMPHEIGHT: 0.000

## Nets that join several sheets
GND: BlueNRG-LP (CN1.7 CN2.6 CN2.7 L2.1), Supply (36 pins), USB_MICRO (36 pins)
VDD_1: BlueNRG-LP (JP1.1 R3.1 R5.2), Supply (25 pins), USB_MICRO (15 pins)
VLDO: Supply (C19.2 JP2.3 U3.1 U3.8), USB_MICRO (R57.2)
BLE_RSTN: BlueNRG-LP (JP5.1 U1.38), Supply (C20.2 R26.2 SW1.3 SW1.4)
NetC17_2: Supply (C17.2 R29.2 U3.4 U3.5), USB_MICRO (C29.1 CN6.1 U8.5)
PA0: BlueNRG-LP (U1.13), Supply (R33.1)
PA1: BlueNRG-LP (R13.1 U1.14), Supply (R35.1)
PA6: BlueNRG-LP (R16.1 U1.19), Supply (R40.2)
PA8: BlueNRG-LP (R24.1 U1.12), USB_MICRO (R48.1)
PA9: BlueNRG-LP (R22.1 U1.11), USB_MICRO (R49.2)
PA10: BlueNRG-LP (U1.10), Supply (C40.2 R31.1 SW2.1 SW2.2), USB_MICRO (R47.1)
PA11: BlueNRG-LP (R1.1 U1.9), USB_MICRO (U7.H7)
PA13: BlueNRG-LP (R4.1 R18.1 U1.7), Supply (R38.2), USB_MICRO (U7.E5)
PA14: BlueNRG-LP (R6.1 U1.6), Supply (R41.1), USB_MICRO (U7.G5)
PA15: BlueNRG-LP (R7.1 U1.5), Supply (R37.2), USB_MICRO (U7.G4)
PB0: BlueNRG-LP (R20.1 U1.4), Supply (R42.1)
PB1: BlueNRG-LP (U1.3), Supply (R51.1)
PB2: BlueNRG-LP (R17.2 U1.2), Supply (R50.1)
PB6: BlueNRG-LP (U1.46), Supply (C41.2 R32.1 SW3.1 SW3.2)
PB8: BlueNRG-LP (R10.1 U1.44), Supply (D2.1)
PB9: BlueNRG-LP (R8.1 U1.43), Supply (D3.1)
PB15: BlueNRG-LP (U1.27), Supply (R39.2)
RSTN: BlueNRG-LP (JP5.2 R9.2), USB_MICRO (R56.1)
SWCLK: BlueNRG-LP (JP3.2), USB_MICRO (R53.2)
SWDIO: BlueNRG-LP (JP4.2), USB_MICRO (R54.1)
